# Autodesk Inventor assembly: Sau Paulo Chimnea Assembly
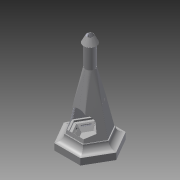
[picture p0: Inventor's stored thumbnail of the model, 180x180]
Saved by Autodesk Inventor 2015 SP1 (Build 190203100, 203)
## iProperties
Created: 2014-12
Part Number: Sau Paulo Chimnea Assembly
Document SubType Name: Assembly
Designer: rsheridan
Author: rsheridan
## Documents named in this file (6)
- \\psf\Home\Documents\Inventor\Sau Paulo Chimnea\Sau Paulo Chimnea Assembly.iam
- \\psf\Home\Documents\Inventor\Sau Paulo Chimnea\Base Assembly.iam
- \\psf\Home\Documents\Inventor\Sau Paulo Chimnea\Upper_Assy.iam
- \\psf\Home\Documents\Inventor\Sau Paulo Chimnea\RivNut.ipt
- \\psf\Home\Documents\Inventor\Sau Paulo Chimnea\ANSI B18.6.7M - M5x0.8 x 6(4).ipt
- \\psf\Home\Documents\Inventor\Sau Paulo Chimnea\Body Assembly New.iam
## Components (11 placed, 5 different names)
1. Base Assembly:1 [sub-assembly] — Mate:1, Mate:2, Mate:3, Mate:6
2. Body Assembly New:1 [sub-assembly] — Mate:1, Mate:2, Mate:3, Mate:4, Mate:5, Insert:1
3. Upper_Assy:1 [sub-assembly] — Mate:4, Mate:5, Mate:6, Insert:2
4. RivNut:1 — Insert:1
5. ANSI B18.6.7M - M5x0.8 x 6(4):1 — Insert:2
6. RivNut:2
7. ANSI B18.6.7M - M5x0.8 x 6(4):2
8. RivNut:4
9. ANSI B18.6.7M - M5x0.8 x 6(4):4
10. RivNut:5
11. ANSI B18.6.7M - M5x0.8 x 6(4):5
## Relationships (8: Mate 6, Insert 2)
- Mate:1: Base Assembly:1 ↔ Body Assembly New:1
- Mate:2: Base Assembly:1 ↔ Body Assembly New:1
- Mate:3: Base Assembly:1 ↔ Body Assembly New:1
- Mate:4: Body Assembly New:1 ↔ Upper_Assy:1
- Mate:5: Body Assembly New:1 ↔ Upper_Assy:1
- Mate:6: Base Assembly:1 ↔ Upper_Assy:1
- Insert:1: Body Assembly New:1 ↔ RivNut:1
- Insert:2: Upper_Assy:1 ↔ ANSI B18.6.7M - M5x0.8 x 6(4):1
